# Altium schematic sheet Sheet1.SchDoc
size A4
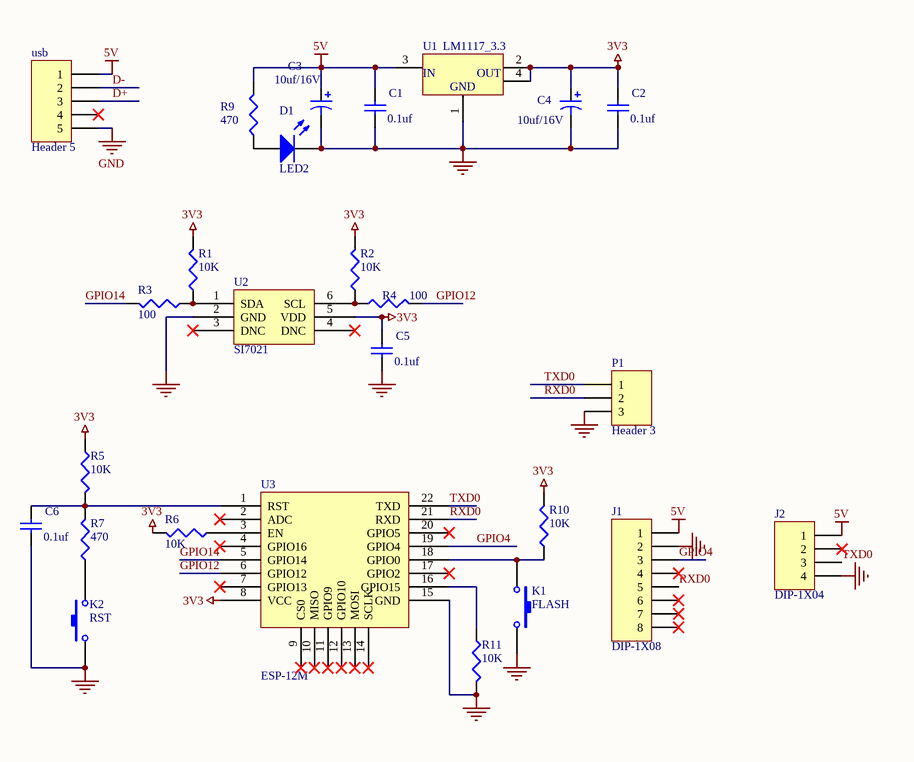
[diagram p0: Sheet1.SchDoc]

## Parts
C1  0.1uf  [0603]
C2  0.1uf  [0603]
C3  10uf/16V  [3528]
C4  10uf/16V  [3528]
C5  0.1uf  [0603]
C6  0.1uf  [0603]
D1  LED2  [0603]
J1  DIP-1X08  [1.27*8]
J2  DIP-1X04  [XH-1X04-2.5]
K1  FLASH  [upkey]
K2  RST  [upkey]
P1  Header 3  [HDR1X3]
R1  10K  [0603]
R2  10K  [0603]
R3  100  [0603]
R4  100  [0603]
R5  10K  [0603]
R6  10K  [0603]
R7  470  [0603]
R9  470  [0603]
R10  10K  [0603]
R11  10K  [0603]
U1  LM1117_3.3  [SOT223]
U2  SI7021  [si7021]
U3  ESP-12M  [wifi]
usb  Header 5  [MICROUSB]

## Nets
3V3: C2.2 C4.1 C5.2 R1.2 R2.2 R5.1 R6.2 R10.2 U1.2(VOUT) U1.4 U2.5(VDD) U3.8(VCC)
5V: C1.2 C3.1 J1.1 J2.1 R9.2 U1.3(VIN) usb.1
GND: C1.1 C2.1 C3.2 C4.2 C5.1 C6.1 D1.2(K) J1.2 J2.4 K1.2 K2.1 P1.3 R11.2 U1.1(GND) U2.2(GND) U3.15(GND) usb.5
D+: usb.3
D-: usb.2
GPIO4: J1.3 U3.19(GPIO4)
GPIO12: R4.2 U3.6(GPIO12)
GPIO14: R3.2 U3.5(GPIO14)
RXD0: J1.5 P1.2 U3.21(RXD)
TXD0: J2.3 P1.1 U3.22(TXD)
NetC6_2: C6.2 R5.2 R7.2 U3.1(RST)
NetD1_1: D1.1(A) R9.1
NetK1_1: K1.1 R10.1 U3.18(GPIO0)
NetK2_2: K2.2 R7.1
NetR1_1: R1.1 R3.1 U2.1(SDA)
NetR2_1: R2.1 R4.1 U2.6(SCL)
NetR6_1: R6.1 U3.3(EN)
NetR11_1: R11.1 U3.16(GPIO15)

Not connected (* = marked no-connect by the designer): J1 4* 6* 7* 8*; J2 2*; U2 3(DNC)* 4(DNC)*; U3 2(ADC)* 4(GPIO16)* 7(GPIO13)* 9(CS0)* 10(MISO)* 11(GPIO9)* 12(GPIO10)* 13(MOSI)* 14(SCLK)* 17(GPIO2)* 20(GPIO5)*; usb 4*

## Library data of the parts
C1 C2 C5 C6 = Cap Semi: Capacitor (Semiconductor SIM Model)
C3 C4 = Cap Pol3: Polarized Capacitor (Surface Mount)
D1 = LED2: Typical RED, GREEN, YELLOW, AMBER GaAs LED
J1 = DIP-1X08: Header, 8-Pin
J2 = DIP-1X04: Header, 4-Pin
K1 K2 = SW
P1 = Header 3: Header, 3-Pin
R1-R7 R9-R11 = Res3: Resistor; Value: 1K
U1 = LM1117
usb = Header 5: Header, 5-Pin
